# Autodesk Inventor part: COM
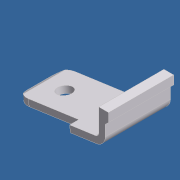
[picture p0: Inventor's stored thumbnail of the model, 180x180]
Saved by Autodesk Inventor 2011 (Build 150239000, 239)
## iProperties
Created: 2008-01
Part Number: COM
Document SubType Name: Modeling
Designer: gstuder
Density: 1 g/cm^3
Author: gstuder
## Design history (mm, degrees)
sketch "Sketch1"
  geometry: L1 (31.75, -2.94)-(31.42, -2.94) reference; L2 (31.42, 0.286)-(31.75, 0.286) reference; L3 (34.29, 10.129)-(34.29, -2.597) reference; L4 (7.62, 12.034)-(32.385, 12.034) reference; L5 (6.35, 7.881)-(6.35, 10.764) reference; L6 (5.08, -0.628)-(5.08, 6.611) reference; L7 (6.35, -1.962)-(6.35, -1.898) reference; L8 (33.02, -3.867)-(8.255, -3.867) reference; L9 (20.066, -3.867)-(20.066, -4.705); L10 (20.066, -4.705)-(19.749, -5.01); L11 (19.749, -5.01)-(19.749, -6.07); L12 (18.874, -7.076)-(10.694, -8.229); L13 (10.605, -7.6)-(18.786, -6.447); L14 (19.114, -6.07)-(19.114, -3.861); L15 (10.138, -7.923)-(10.156, -8.048); L16 (10.694, -8.229)-(10.156, -8.048); L17 (10.605, -7.6)-(10.138, -7.923); L18 (20.066, -3.867)-(19.114, -3.861); C1 r 1.613 at (8.89, 9.494) reference; A1 r 1.613 centre (31.75, -1.327) between (31.75, -2.94) and (31.75, 0.286) reference; A2 r 1.613 centre (31.42, -1.327) between (31.42, 0.286) and (31.42, -2.94) reference; A3 r 1.905 centre (32.385, 10.129) between (34.29, 10.129) and (32.385, 12.034) reference; A4 r 1.27 centre (7.62, 10.764) between (7.62, 12.034) and (6.35, 10.764) reference; A5 r 1.27 centre (6.35, 6.611) between (6.35, 7.881) and (5.08, 6.611) reference; A6 r 1.27 centre (6.35, -0.628) between (5.08, -0.628) and (6.35, -1.898) reference; A7 r 1.905 centre (8.255, -1.962) between (6.35, -1.962) and (8.255, -3.867) reference; A8 r 1.27 centre (33.02, -2.597) between (33.02, -3.867) and (34.29, -2.597) reference; A9 r 1.016 centre (18.733, -6.07) between (18.874, -7.076) and (19.749, -6.07); A10 r 0.381 centre (18.733, -6.07) between (18.786, -6.447) and (19.114, -6.07); 4 further points
  constraints: 20 end point, 9 point on line, 4 point on circle, 4 tangent, 3 parallel, 2 centre point, 2 perpendicular
  dimensions: "d0" = 0.9525 distance between parallel lines of L9 L14; "thick" = 0.635 distance between parallel lines of L14 L11; "d3" = 0.635 distance between parallel lines of L13 L12 (= thick); "d10" = 9.652 distance from line of point (19.749, -6.953) L15; "d11" = 2.54 distance of point (19.114, -6.401) L14.end; "d12" = 3.81 vertical distance of L14.end point (10.102, -7.671); "d13" = 3.0861 vertical distance of L9.start point (19.749, -6.953); "d14" = 0.8382 distance of L9.start L9.end; "d15" = 1.143 vertical distance of L9.start L10.end; "d16" = 14.224 distance between parallel lines of L9 L3; "d17" = 0.508 distance of L12.end point (10.191, -8.3); "d18" = 0.254 distance of L15.end point (10.191, -8.3); "d19" = 0.508 distance of L13.start point (10.102, -7.671); "d20" = 0.254 distance of L15.start point (10.102, -7.671); "d21" = 1.016 radius of A9; "d23" = 0.635 radial gap between concentric circles of A9 A10 (= thick)
extrude "Extrusion1" new body sketch "Sketch1" distance "d24" = 6.35; taper "d25" = 0 deg
sketch "Sketch2"
  geometry: L1 (0, 6.35)-(0, 0) reference; L2 (-8.261, 6.35)-(0, 6.35) reference; L3 (-8.769, 0)-(-2.54, 0); L4 (-2.54, 0)-(-2.54, 0.889); L5 (-2.54, 0.889)-(-7.499, 0.889); L6 (-8.769, 2.159)-(-8.769, 0); L7 (-8.769, 6.35)-(-2.54, 6.35); L8 (-2.54, 6.35)-(-2.54, 5.461); L9 (-2.54, 5.461)-(-7.499, 5.461); L10 (-8.769, 4.191)-(-8.769, 6.35); L11 (-8.261, 0)-(0, 0) reference; L12 (0, 6.35)-(0, 0) reference; L13 (-8.261, 6.35)-(0, 6.35) reference; L14 (-8.261, 6.35)-(-8.261, 0) reference; C1 r 0.698 at (-6.229, 3.175); A1 r 1.27 centre (-7.499, 4.191) between (-7.499, 5.461) and (-8.769, 4.191); A2 r 1.27 centre (-7.499, 2.159) between (-8.769, 2.159) and (-7.499, 0.889)
  constraints: 16 end point, 4 parallel, 4 point on circle, 3 centre point, 2 collinear, 2 horizontal, 2 perpendicular, 2 tangent, 1 equal radius, 1 point on line
  dimensions: "d26" = 4.572 distance between parallel lines of L5 L9; "d27" = 2.54 distance between parallel lines of L1 L8; "d28" = 2.54 distance between parallel lines of L4 L1 (= d27); "d29" = 0.889 distance between parallel lines of L2 L9 (computed from d26); "d31" = 2.286 distance from line of L5 C1.centre; "d32" = 1.397 diameter of C1; "d35" = 1.27 radius of A1; "d37" = 6.22915 distance of L3.start L3.end; "d38" = 2.54 distance from line of L10 C1.centre; "d39" = 1.27 horizontal distance of L10.start L9.end (derived); "d40" = 1.27 horizontal distance of L5.end L6.start
extrude "Extrusion2" cut sketch "Sketch2" stored distance "d43" = 6.35; taper "d44" = 0 deg
body "Solid1"
node "Reference1"
node "Projected Loop1"
